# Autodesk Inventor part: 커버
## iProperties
Company: 한국ATC센터
Created: 2015-04
Part Number: 커버
Document SubType Name: Modeling
Designer: KYOUNG IL JANG
Density: 1 g/cm^3
Material: 기본값
Mass: 394.015 g
Surface Area: 1019.6 cm^2
Volume: 394.015 cm^3
Author: KYOUNG IL JANG
